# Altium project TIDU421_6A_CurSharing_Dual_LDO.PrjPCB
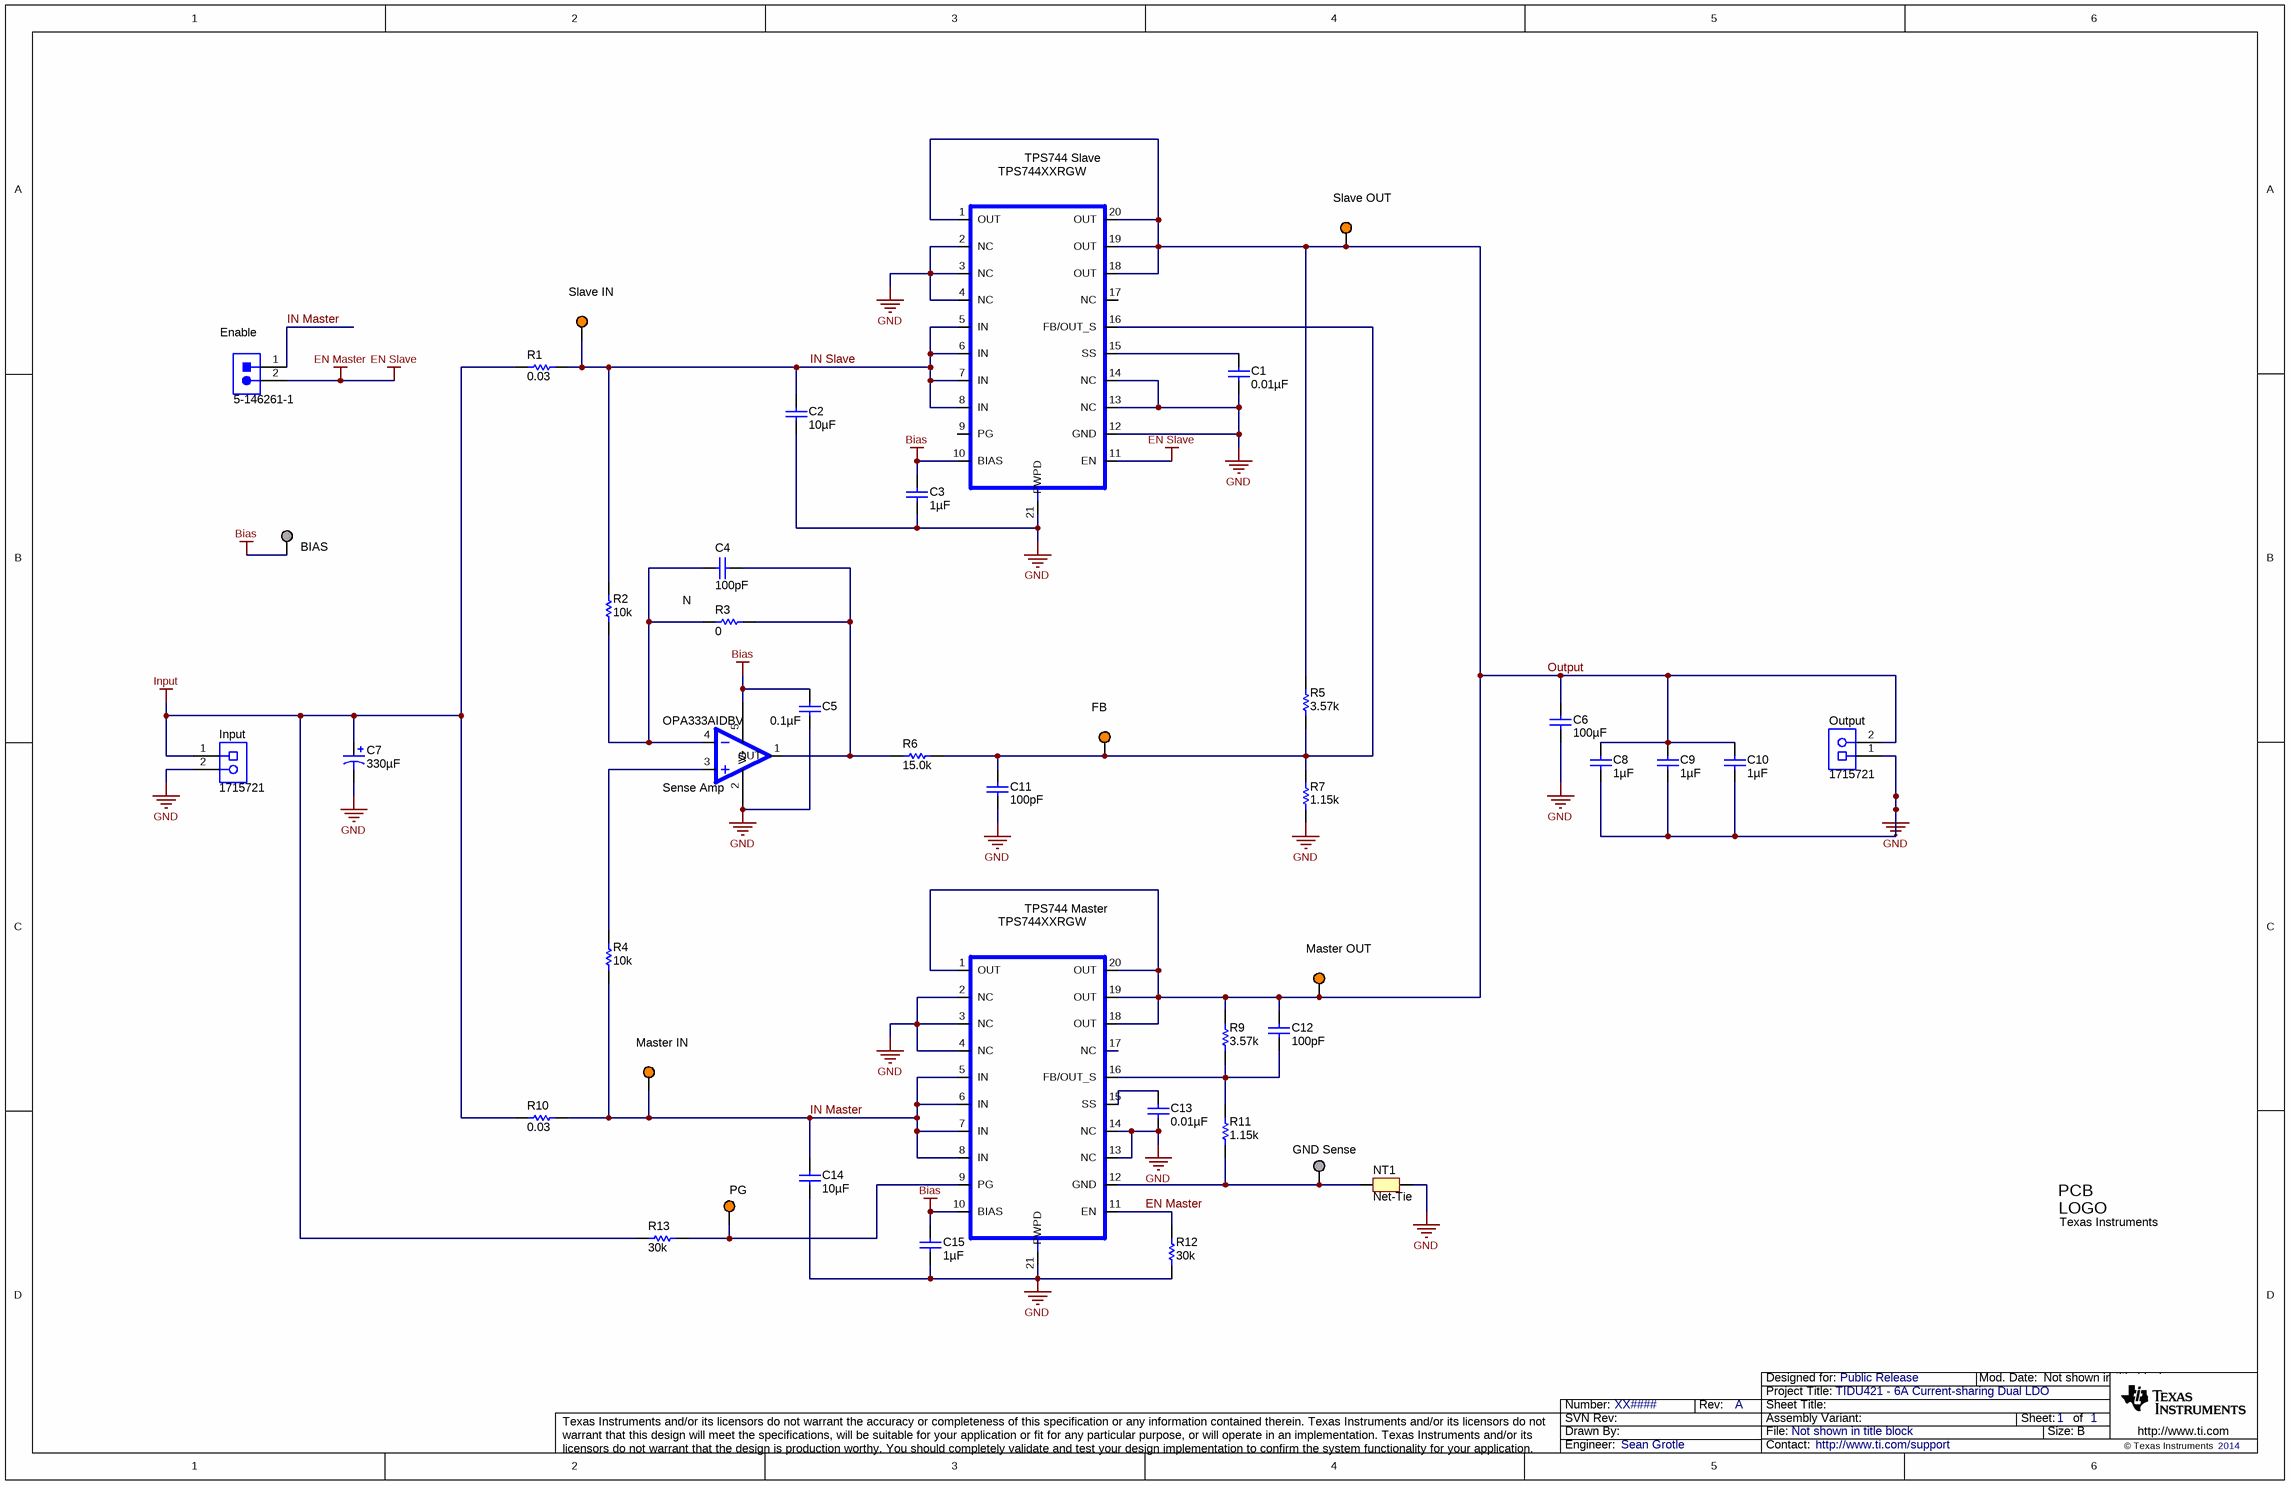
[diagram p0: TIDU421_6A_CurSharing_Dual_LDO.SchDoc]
CopyrightYear: 2014; PCB_Layout: Sean Grotle; PCB_Rev: A; PRJ_Customer: Public Release; PRJ_Engineer: Sean Grotle; PRJ_Number: XX####; PRJ_Title: TIDU421 - 6A Current-sharing Dual LDO; SCH_Rev: A; TechSupport: http://www.ti.com/support
1 sheet, 43 parts. Net scope: global (net labels, ports and power ports of the same name join across sheets).
Board file: TIDU421_6A_CurSharing_Dual_LDO.PcbDoc

## Sheet TIDU421_6A_CurSharing_Dual_LDO.SchDoc
size 431 x 279 mm; Date: Not shown in title block; ApprovedBy: Not shown in title block; CheckedBy: Not shown in title block; Author: Not shown in title block; CompanyName: Not shown in title block; Engineer: Not shown in title block; Organization: Not shown in title block; Address1: Not shown in title block; Address2: Not shown in title block; Address3: Not shown in title block; Address4: Not shown in title block; DocumentNumber: 1; Revision: Use project parameter SCH_Rev; SheetNumber: 1; SheetTotal: 1; PageSetup: Record=PageOptions|CenterHorizontal=True|CenterVertical=True|PrintScale=0.96|XCorrection=1.00|YCorrection=1.00|PrintKind=0|BorderSize=5000000|LeftOffset=0|BottomOffset=0|Orientation=2|PaperLength=1000|PaperWidth=1000|Scale=100|PaperSource=15|PrintQuality=600|MediaType=1|DitherType=10|PaperKind=11x17|PrintScaleMode=1

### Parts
BIAS  Suggest using a net name here  [Keystone_1562-2]  (value not drawn)
C1  ValueDisplayed: 0.01µF  [0603]  (hidden comment: GRM188R71E103KA01D)
C2  ValueDisplayed: 10µF  [1206]  (hidden comment: C3216X5R1A106M)
C3  ValueDisplayed: 1µF  [0805_HV]  (hidden comment: GRM21BR71C105KA01L)
C4  N  ValueDisplayed: 100pF  [0603]
C5  ValueDisplayed: 0.1µF  [0603]  (hidden comment: GRM188R61C104KA01D)
C6  ValueDisplayed: 100µF  [1206]  (hidden comment: GRM31CR60J107ME39L)
C7  ValueDisplayed: 330µF  [CAPSMT_62_J80]  (hidden comment: APXA100ARA331MJ80G)
C8  ValueDisplayed: 1µF  [0805_HV]  (hidden comment: GRM21BR71C105KA01L)
C9  ValueDisplayed: 1µF  [0805_HV]  (hidden comment: GRM21BR71C105KA01L)
C10  ValueDisplayed: 1µF  [0805_HV]  (hidden comment: GRM21BR71C105KA01L)
C11  ValueDisplayed: 100pF  [0603]  (hidden comment: 06033C101KAT2A)
C12  ValueDisplayed: 100pF  [0603]  (hidden comment: 06033C101KAT2A)
C13  ValueDisplayed: 0.01µF  [0603]  (hidden comment: GRM188R71E103KA01D)
C14  ValueDisplayed: 10µF  [1206]  (hidden comment: C3216X5R1A106M)
C15  ValueDisplayed: 1µF  [0805_HV]  (hidden comment: GRM21BR71C105KA01L)
Enable  5-146261-1  [CONN_5-146261-1]
FB  5003  [Keystone5003]  (value not drawn)
GND_Sense  Suggest using a net name here  [Keystone_1562-2]  (value not drawn)
Input  1715721  [PhoenixContact_1715721]
Logo1  Texas Instruments  [TI_Stacked_SolderMask_Small]  (no BOM)
Master_IN  5003  [Keystone5003]  (value not drawn)
Master_OUT  5003  [Keystone5003]  (value not drawn)
NT1  Net-Tie  [Net-Tie_10mil]  (net tie, no BOM)
Output  1715721  [PhoenixContact_1715721]
PG  5003  [Keystone5003]  (value not drawn)
R1  value 0.03  [2010M]  (hidden comment: LVK20R030FER)
R2  value 10k  [0603]  (hidden comment: RC0603JR-0710KL)
R3  value 0  [0603]  (hidden comment: CRCW06030000Z0EA)
R4  value 10k  [0603]  (hidden comment: RC0603JR-0710KL)
R5  value 3.57k  [0603]  (hidden comment: RC0603FR-073K57L)
R6  value 15.0k  [0603]  (hidden comment: RC0603FR-0715KL)
R7  value 1.15k  [0603]  (hidden comment: CRCW06031K15FKEA)
R9  value 3.57k  [0603]  (hidden comment: RC0603FR-073K57L)
R10  value 0.03  [2010M]  (hidden comment: LVK20R030FER)
R11  value 1.15k  [0603]  (hidden comment: CRCW06031K15FKEA)
R12  value 30k  [0603]  (hidden comment: RC0603JR-0730KL)
R13  value 30k  [0603]  (hidden comment: RC0603JR-0730KL)
Sense_Amp  OPA333AIDBV  [SOT23-5P]
Slave_IN  5003  [Keystone5003]  (value not drawn)
Slave_OUT  5003  [Keystone5003]  (value not drawn)
TPS744_Master  TPS744XXRGW  [RGW20]
TPS744_Slave  TPS744XXRGW  [RGW20]

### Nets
Bias: BIAS.1 C3.1 C5.1 C15.1 Sense_Amp.5(V+) TPS744_Master.10(BIAS) TPS744_Slave.10(BIAS)
EN Master: Enable.2 R12.2 TPS744_Master.11(EN) TPS744_Slave.11(EN)  [also labelled EN Slave]
GND: C1.2 C2.2 C3.2 C5.2 C6.2 C7.2(-) C8.2 C9.2 C10.2 C11.2 C13.2 C14.2 C15.2 Input.2 NT1.2 Output.1 R7.1 R12.1 Sense_Amp.2(V-) TPS744_Master.2(NC) TPS744_Master.3(NC) TPS744_Master.4(NC) TPS744_Master.13(NC) TPS744_Master.14(NC) TPS744_Master.21(PWPD) TPS744_Slave.2(NC) TPS744_Slave.3(NC) TPS744_Slave.4(NC) TPS744_Slave.12(GND) TPS744_Slave.13(NC) TPS744_Slave.14(NC) TPS744_Slave.21(PWPD)
Input: C7.1(+) Input.1 R1.1 R10.1 R13.2
IN Master: C14.1 Enable.1 Master_IN.1 R4.1 R10.2 TPS744_Master.5(IN) TPS744_Master.6(IN) TPS744_Master.7(IN) TPS744_Master.8(IN)
IN Slave: C2.1 R1.2 R2.2 Slave_IN.1 TPS744_Slave.5(IN) TPS744_Slave.6(IN) TPS744_Slave.7(IN) TPS744_Slave.8(IN)
Output: C6.1 C8.1 C9.1 C10.1 C12.1 Master_OUT.1 Output.2 R5.2 R9.2 Slave_OUT.1 TPS744_Master.1(OUT) TPS744_Master.18(OUT) TPS744_Master.19(OUT) TPS744_Master.20(OUT) TPS744_Slave.1(OUT) TPS744_Slave.18(OUT) TPS744_Slave.19(OUT) TPS744_Slave.20(OUT)
NetC1_1: C1.1 TPS744_Slave.15(SS)
NetC4_1: C4.1 R3.2 R6.1 Sense_Amp.1(OUT)
NetC4_2: C4.2 R2.1 R3.1 Sense_Amp.4
NetC11_1: C11.1 FB.1 R5.1 R6.2 R7.2 TPS744_Slave.16(FB/OUT_S)
NetC12_2: C12.2 R9.1 R11.2 TPS744_Master.16(FB/OUT_S)
NetC13_1: C13.1 TPS744_Master.15(SS)
NetGND_Sense_1: GND_Sense.1 NT1.1 R11.1 TPS744_Master.12(GND)
NetPG_1: PG.1 R13.1 TPS744_Master.9(PG)
NetR4_2: R4.2 Sense_Amp.3

Not connected (* = marked no-connect by the designer): TPS744_Master 17(NC); TPS744_Slave 9(PG) 17(NC)

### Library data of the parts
BIAS GND_Sense = 1562-2: Terminal, Turret, TH, Hollow, Single; Manufacturer: Keystone; CompType: Turret Terminal; U/M: EA
C1 C13 = GRM188R71E103KA01D: CAP, CERM, 0.01uF, 25V, +/-10%, X7R, 0603; Manufacturer: MuRata; Polarized: N; CompType: Capacitor; U/M: EA; Cap_F: 0.00000001; Tolerance_%: 10; Value1: Unknown; VDC_V: 25; TaMin_C: -55; TaMax_C: 125
C2 C14 = C3216X5R1A106M: CAP, CERM, 10uF, 10V, +/-20%, X5R, 1206; Manufacturer: TDK; Polarized: N; CompType: Capacitor; U/M: EA; Cap_F: 0.00001; Tolerance_%: 20; ESR_Ohm: 0.0046; Value1: 0.0046 ohm; VDC_V: 10; IRMS_A: 2.7; TaMin_C: -55; TaMax_C: 85
C3 C8-C10 C15 = GRM21BR71C105KA01L: CAP, CERM, 1uF, 16V, +/-10%, X7R, 0805; Manufacturer: MuRata; Polarized: N; CompType: Capacitor; U/M: EA; Cap_F: 0.000001; Tolerance_%: 10; ESR_Ohm: 0.003; Value1: 0.003 ohm; VDC_V: 16; TaMin_C: -55; TaMax_C: 125; Cap_Case: 0805
C4 = 06033C101KAT2A: CAP, CERM, 100pF, 25V, +/-10%, X7R, 0603; Manufacturer: AVX; CompType: Capacitor; U/M: EA; Cap_F: 0.0000000001; Tolerance_%: 10; Value1: Unknown; VDC_V: 25; TaMin_C: -55; TaMax_C: 125
C5 = GRM188R61C104KA01D: CAP, CERM, 0.1uF, 16V, +/-10%, X5R, 0603; Manufacturer: MuRata; Polarized: N; CompType: Capacitor; U/M: EA; Cap_F: 0.0000001; Tolerance_%: 10; Value1: Unknown; VDC_V: 16; TaMin_C: -55; TaMax_C: 85
C6 = GRM31CR60J107ME39L: CAP, CERM, 100uF, 6.3V, +/-20%, X5R, 1206; Manufacturer: MuRata; Polarized: N; CompType: Capacitor; U/M: EA; Cap_F: 0.0001; Tolerance_%: 20; ESR_Ohm: 0.003; Value1: 0.003 ohm; VDC_V: 6.3; TaMin_C: -55; TaMax_C: 85
C7 = APXA100ARA331MJ80G: CAP, AL, 330uF, 10V, +/-20%, 0.024 ohm, SMD; Manufacturer: Nippon Chemi-Con; Polarized: Y; CompType: Capacitor; U/M: EA; Cap_F: 0.00033; Tolerance_%: 20; VDC_V: 10; ESR_Ohm: 0.024; IRMS_A: 3.77; TaMin_C: -55; TaMax_C: 105; Cap_Case: J80
C11 C12 = 06033C101KAT2A: CAP, CERM, 100pF, 25V, +/-10%, X7R, 0603; Manufacturer: AVX; Polarized: N; CompType: Capacitor; U/M: EA; Cap_F: 0.0000000001; Tolerance_%: 10; Value1: Unknown; VDC_V: 25; TaMin_C: -55; TaMax_C: 125
Enable = 5-146261-1: Header, 100mil, 2x1, Gold plated, TH; Manufacturer: TE Connectivity; SymbolCreator: a0412235; U/M: EA
FB Master_IN Master_OUT PG Slave_IN Slave_OUT = 5003: Test Point, Miniature, Orange, TH; Manufacturer: Keystone; CompType: Test Point Loop; U/M: EA
Input Output = 1715721: Conn Term Block, 2POS, 5.08mm, TH; Manufacturer: Phoenix Contact; SymbolCreator: a0412235; Value: 2x1; CompType: Terminal Block; U/M: EA
Logo1 = TI_Logo: Texas Instrument Corporate Signature; SymbolCreator: codlsc
NT1 = Net-Tie: Single point connection between nets.; SymbolCreator: codlsc
R1 R10 = LVK20R030FER: RES, 0.03 ohm, 1%, 0.75W, 2010; Manufacturer: Ohmite; CompType: Resistor; Value_Code: R030; Tolerance_%: 1; Power_W: 0.75; TempCo: 50 ppm/C; EIA_Code: E96; U/M: EA
R2 R4 = RC0603JR-0710KL: RES, 10k ohm, 5%, 0.1W, 0603; Manufacturer: Yageo America; CompType: Resistor; Res_ohm: 10000; Value_Code: 10k0; Tolerance_%: 5; Power_W: 0.1; VDC_V: 50; TempCo: 100 ppm/C; EIA_Code: E24; U/M: EA
R3 = CRCW06030000Z0EA: RES, 0 ohm, 5%, 0.1W, 0603; Manufacturer: Vishay-Dale; CompType: Resistor; Value_Code: 0000; Tolerance_%: 5; Power_W: 0.1; VDC_V: 75; TempCo: 200 ppm/C; EIA_Code: E24; U/M: EA
R5 R9 = RC0603FR-073K57L: RES, 3.57k ohm, 1%, 0.1W, 0603; Manufacturer: Yageo America; CompType: Resistor; Res_ohm: 3570; Value_Code: 3k57; Tolerance_%: 1; Power_W: 0.1; VDC_V: 150; TempCo: 200 ppm/C; EIA_Code: E96; U/M: EA
R6 = RC0603FR-0715KL: RES, 15.0k ohm, 1%, 0.1W, 0603; Manufacturer: Yageo America; CompType: Resistor; Res_ohm: 15000; Value_Code: 15k0; Tolerance_%: 1; Power_W: 0.1; VDC_V: 150; TempCo: 200 ppm/C; EIA_Code: E96; U/M: EA
R7 R11 = CRCW06031K15FKEA: RES, 1.15k ohm, 1%, 0.1W, 0603; Manufacturer: Vishay-Dale; CompType: Resistor; Res_ohm: 1150; Value_Code: 1k15; Tolerance_%: 1; Power_W: 0.1; VDC_V: 75; TempCo: 100 ppm/C; EIA_Code: E96; U/M: EA
R12 R13 = RC0603JR-0730KL: RES, 30k ohm, 5%, 0.1W, 0603; Manufacturer: Yageo America; CompType: Resistor; Res_ohm: 30000; Value_Code: 30k0; Tolerance_%: 5; Power_W: 0.1; VDC_V: 50; TempCo: 100 ppm/C; EIA_Code: E24; U/M: EA
Sense_Amp = OPA333AIDBV: IC, 1.8V, microPower, CMOS Op Amp, Zerø-Drift Series; Manufacturer: TI; Alternate Manufacturer: None; Area: 31500
TPS744_Master TPS744_Slave = TPS744XXRGW: IC, 1.5a LDO With Programmable Sequencing; Manufacturer: TI; Alternate Manufacturer: None; Area: 56644

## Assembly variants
001: not fitted C4 C11 C12 R3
